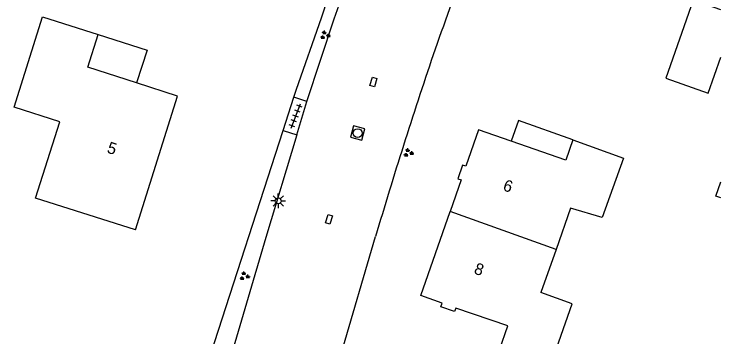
# Model space of a CAD drawing. Extents: x 128999 to 131010, y 395498 to 399007.
# Drawn here: x 130939.4 to 131000, y 396875.4 to 396903.1 of the extents above; entities that cross this region are included whole.
import ezdxf

# ---------------------------------------------------------------- set-up
doc = ezdxf.new("R2010")
doc.units = 0
for name, color, linetype in [('gg-afsc-erfafscheiding', 7, 'Continuous'), ('gg-anno-huisnummerreeks BGT', 7, 'Continuous'), ('gg-bbg-gedigitaliseerde bebouwing', 7, 'Continuous'), ('gg-bbg-gedigitaliseerde bijgebouw', 7, 'Continuous'), ('gg-bbg-hoofdgebouw', 7, 'Continuous'), ('gg-bbg-luifel en loopbrug', 7, 'Continuous'), ('gg-bbg-tussenscheiding', 7, 'Continuous'), ('gg-knt-verharding', 7, 'Continuous'), ('gt-grn-groengrens', 7, 'Continuous'), ('gt-grn-weggrens', 7, 'Continuous'), ('gt-symb-groenvak', 7, 'Continuous'), ('gt-symb-kolk center center', 7, 'Continuous'), ('gt-symb-lichtmast', 7, 'Continuous'), ('gt-symb-rioolschacht', 7, 'Continuous'), ('gt-symb-tegel verharding', 7, 'Continuous')]:
    doc.layers.add(name, color=color, linetype=linetype)

# ---------------------------------------------------------------- blocks, each defined once
blk = doc.blocks.new('gt0-TEG1')
at = {"layer": 'gt-symb-tegel verharding'}
for p, q in [((-1.125, 0), (1.125, 0)), ((-0.9, -0.25), (-0.9, 0.25)), ((-0.45, -0.25), (-0.45, 0.25)), ((0, -0.25), (0, 0.25)), ((0.45, -0.25), (0.45, 0.25)), ((0.9, -0.25), (0.9, 0.25))]:
    blk.add_line(p, q, dxfattribs=at)
blk = doc.blocks.new('gt0-KOLKCC')
at = {"layer": 'gt-symb-kolk center center'}
blk.add_lwpolyline([(-0.375, 0.2), (0.375, 0.2), (0.375, -0.2), (-0.375, -0.2)], close=True, dxfattribs=at)
blk = doc.blocks.new('gt0-GRVAK')
at = {"layer": 'gt-symb-groenvak'}
for p, q in [((-0.11, 0.189), (-0.228, 0.24)), ((-0.182, 0.153), (0.088, 0.153)), ((-0.091, 0.211), (-0.156, 0.322)), ((-0.047, 0.214), (-0.047, 0.393)), ((-0.004, 0.211), (0.061, 0.322)), ((0.015, 0.189), (0.133, 0.24)), ((0.262, -0.052), (0.197, 0.059)), ((0.305, -0.049), (0.305, 0.13)), ((0.349, -0.052), (0.414, 0.059)), ((-0.245, -0.228), (-0.363, -0.177)), ((-0.318, -0.264), (-0.047, -0.264)), ((-0.226, -0.206), (-0.291, -0.095)), ((-0.183, -0.203), (-0.183, -0.024)), ((-0.139, -0.206), (-0.074, -0.095)), ((-0.12, -0.228), (-0.002, -0.177)), ((0.243, -0.074), (0.125, -0.023)), ((0.17, -0.11), (0.441, -0.11)), ((0.368, -0.074), (0.486, -0.023))]:
    blk.add_line(p, q, dxfattribs=at)
blk = doc.blocks.new('gt0-LMAST')
at = {"layer": 'gt-symb-lichtmast'}
for p, q in [((-0.005, 0.246), (-0.005, 0.621)), ((-0.182, 0.173), (-0.447, 0.438)), ((0.172, 0.173), (0.437, 0.438)), ((-0.255, -0.004), (-0.63, -0.004)), ((-0.182, -0.181), (-0.447, -0.446)), ((-0.005, -0.254), (-0.005, -0.629)), ((0.437, -0.446), (0.172, -0.181)), ((0.245, -0.004), (0.62, -0.004))]:
    blk.add_line(p, q, dxfattribs=at)
blk.add_circle((-0.005, -0.004), 0.25, dxfattribs=at)
blk = doc.blocks.new('gt0-RS')
at = {"layer": 'gt-symb-rioolschacht'}
blk.add_lwpolyline([(-0.5, -0.5), (0.5, -0.5), (0.5, 0.5), (-0.5, 0.5)], close=True, dxfattribs=at)
blk.add_circle((0, 0), 0.375, dxfattribs=at)

msp = doc.modelspace()

# ---------------------------------------------------------------- linework, layer by layer
at = {"layer": 'gg-afsc-erfafscheiding'}
for p, q in [((130963.595, 396896.632), (130965.73, 396902.759)), ((130954.339, 396868.09), (130962.43, 396893.094))]:
    msp.add_line(p, q, dxfattribs=at)
at = {"layer": 'gg-bbg-gedigitaliseerde bebouwing'}
for p, q in [((130982.006, 396892.167), (130979.19, 396893.14)), ((130985.86, 396882.899), (130984.561, 396879.186))]:
    msp.add_line(p, q, dxfattribs=at)
for points in [[(130949.77, 396884.58), (130941.199, 396887.282), (130943.268, 396893.838), (130939.352, 396895.074), (130941.8, 396902.83), (130946.57, 396901.33)], [(130987.304, 396892.273), (130986.687, 396890.55), (130982.006, 396892.167)], [(130987.304, 396892.273), (130991.632, 396890.721), (130989.826, 396885.62), (130987.095, 396886.431), (130985.86, 396882.899)], [(130985.31, 396872.77), (130987.233, 396878.235), (130984.561, 396879.186)]]:
    msp.add_lwpolyline(points, dxfattribs=at)
at = {"layer": 'gg-bbg-gedigitaliseerde bijgebouw'}
for points in [[(131000, 396903.425), (130997.63, 396904.26), (130995.276, 396897.584), (130998.917, 396896.3), (131000, 396899.373)], [(131000, 396887.321), (130999.576, 396887.469), (131000, 396888.687)]]:
    msp.add_lwpolyline(points, dxfattribs=at)
at = {"layer": 'gg-bbg-hoofdgebouw'}
for points in [[(130949.854, 396897.165), (130945.68, 396898.52), (130946.57, 396901.33)], [(130949.77, 396884.58), (130953.38, 396896.02), (130949.854, 396897.165)], [(130979.19, 396893.14), (130978.12, 396890.03), (130977.84, 396890.12), (130977.43, 396888.95), (130977.72, 396888.86), (130976.767, 396886.134)], [(130985.31, 396872.77), (130981.007, 396874.284), (130981.708, 396876.347), (130977.248, 396877.844), (130977.147, 396877.562), (130975.98, 396877.98), (130976.09, 396878.29), (130974.25, 396878.93), (130976.767, 396886.134)]]:
    msp.add_lwpolyline(points, dxfattribs=at)
at = {"layer": 'gg-bbg-luifel en loopbrug'}
for points in [[(130946.57, 396901.33), (130950.764, 396899.968), (130949.854, 396897.165)], [(130987.304, 396892.273), (130982.643, 396893.943), (130982.006, 396892.167)]]:
    msp.add_lwpolyline(points, dxfattribs=at)
at = {"layer": 'gg-bbg-tussenscheiding'}
msp.add_line((130985.86, 396882.899), (130976.767, 396886.134), dxfattribs=at)
at = {"layer": 'gg-knt-verharding'}
for p, q in [((130964.483, 396895.574), (130963.367, 396895.941)), ((130963.617, 396892.719), (130964.483, 396895.574)), ((130962.43, 396893.094), (130963.617, 396892.719)), ((130966.577, 396871.124), (130970.364, 396883.989))]:
    msp.add_line(p, q, dxfattribs=at)
for points in [[(130964.483, 396895.574), (130966.82, 396902.658), (130968.106, 396906.28)], [(130963.617, 396892.719), (130960.95, 396883.919), (130957.476, 396872.165), (130954.992, 396864.034), (130949.508, 396847.557), (130945.122, 396835.893)]]:
    msp.add_lwpolyline(points, dxfattribs=at)
for centre, radius, start, end in [((131559.643, 396695.672), 618.878, 159.207914, 160.76474), ((131373.462, 396764.391), 420.466, 161.24795, 163.47458)]:
    msp.add_arc(centre, radius, start, end, dxfattribs=at)
at = {"layer": 'gt-grn-groengrens'}
for p, q in [((130965.73, 396902.759), (130966.898, 396906.314)), ((130963.367, 396895.941), (130963.595, 396896.632))]:
    msp.add_line(p, q, dxfattribs=at)
at = {"layer": 'gt-grn-weggrens'}
msp.add_line((130962.43, 396893.094), (130963.367, 396895.941), dxfattribs=at)

# ---------------------------------------------------------------- block references
at = {"layer": 'gt-symb-groenvak'}
for p in [(130966.025, 396901.255), (130973.171, 396891.175), (130959.107, 396880.606)]:
    msp.add_blockref('gt0-GRVAK', p, dxfattribs=at)
at = {"layer": 'gt-symb-kolk center center'}
for p, rotation in [((130970.188, 396897.255), 73.1964519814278), ((130966.379, 396885.473), 72.12657893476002)]:
    msp.add_blockref('gt0-KOLKCC', p, dxfattribs=dict(at, rotation=rotation))
at = {"layer": 'gt-symb-lichtmast'}
msp.add_blockref('gt0-LMAST', (130962.019, 396887.056), dxfattribs=at)
at = {"layer": 'gt-symb-rioolschacht', "rotation": 74.93576605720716}
msp.add_blockref('gt0-RS', (130968.832, 396892.865), dxfattribs=at)
at = {"layer": 'gt-symb-tegel verharding', "rotation": 69.2092747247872}
msp.add_blockref('gt0-TEG1', (130963.515, 396894.326), dxfattribs=at)

# ---------------------------------------------------------------- texts
at = {"layer": 'gg-anno-huisnummerreeks BGT'}
for s, rotation, p in [('5', 342.5, (130947.258, 396891.2)), ('6', 340.9, (130981.229, 396887.984)), ('8', 340.7, (130978.745, 396880.847))]:
    msp.add_text(s, height=1, rotation=rotation, dxfattribs=at).set_placement(p)

doc.saveas('drawing.dxf')
